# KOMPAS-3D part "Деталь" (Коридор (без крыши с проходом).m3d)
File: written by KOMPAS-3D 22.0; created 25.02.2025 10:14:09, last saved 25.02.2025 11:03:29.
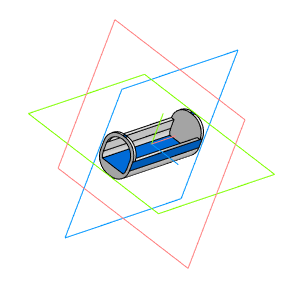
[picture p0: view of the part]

Document properties: Автор: Пользователь Windows; Полное имя файла: C:\Users\Student\Documents\Картошечка\База Сабнатика\Коридор\Коридор (без крыши с проходом).m3d

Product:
- Part/product: Деталь
    Масса: 0.008932

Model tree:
1. Эскиз:1
2. Элемент выдавливания:1
     Расстояние 1 = 30
3. Эскиз:2  (with: Элемент выдавливания:1)
4. Элемент выдавливания:2
     Расстояние 2 = 5
5. Оболочка:1  (with: Элемент выдавливания:2)
     Толщина стенки 2 = 1
6. Эскиз:3  (with: Оболочка:1)
7. Элемент выдавливания:3
     Расстояние 1 = 28
8. Эскиз:4  (with: Оболочка:1)
9. Элемент выдавливания:4
     Расстояние 2 = 1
